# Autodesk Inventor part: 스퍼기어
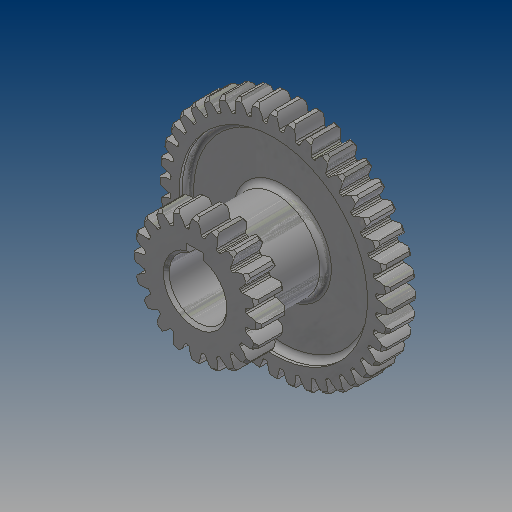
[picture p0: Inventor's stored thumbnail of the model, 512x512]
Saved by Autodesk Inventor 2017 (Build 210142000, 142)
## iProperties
Created: 2015-09
Part Number: 스퍼기어
Material: 강철, 연강
Document SubType Name: Modeling
Designer: mduedu
Density: 7.86 g/cm^3
Mass: 345.726 g
Surface Area: 225.641 cm^2
Volume: 43.9855 cm^3
Appearance: 강철
Author: mduedu
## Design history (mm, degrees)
sketch "스케치1"
  geometry: C1 r 38 at (0, 0); C2 r 40 at (0, 0); C3 r 35.5 at (0, 0); 1 further point
  constraints: 3 centre point, 3 coincident
  dimensions: "d0" = 76 diameter of C1; "d2" = 2 radial gap between concentric circles of C2 C1; "d3" = 71 diameter of C3 (computed from d0)
extrude "돌출1" new body sketch "스케치1" stored distance "d4" = 10; taper "d5" = 0 deg
sketch "스케치2"
  geometry: L1 (0, 35.5)-(0, -35.5); L2 (0, 0)-(40, 0); L3 (0, 0.57)-(39.996, 0.57); L4 (0, 1.57)-(39.969, 1.57); L5 (0, 2.07)-(39.946, 2.07); A1 r 35.5 centre (0, 0) between (0, 35.5) and (0, -35.5) reference; A2 r 40 centre (0, 0) between (40, 0) and (39.946, 2.07) reference; A3 r 9.234 centre (34.93, -7.149) between (39.996, 0.57) and (35.44, 2.07); A4 r 9.234 centre (34.93, 7.149) between (35.44, -2.07) and (39.996, -0.57); A5 r 40 centre (0, 0) between (39.996, -0.57) and (39.996, 0.57); A6 r 35.5 centre (0, 0) between (35.44, -2.07) and (35.44, 2.07); 4 further points
  constraints: 16 point on circle, 10 end point, 6 point on line, 4 centre point, 3 coincident, 3 parallel, 3 symmetric about line, 2 midpoint, 1 perpendicular, 1 vertical, 3 other
  dimensions: "d6" = 0.5 distance between parallel lines of L4 L5; "d8" = 1 distance between parallel lines of L3 L4; "d9" = 1.57 distance between parallel lines of L2 L4
extrude "돌출2" join sketch "스케치2" distance "d10" = 5; taper "d12" = 0 deg; dims "d11" = 5, "d13" = 0
fillet "모깎기1" dims "d17" = 0.5
chamfer "모따기1" distance "d21" = 1; stored, may be unused: second distance "d22" = 2, angle "d23" = 45 deg
sketch "스케치3"
  geometry: C1 r 32.5 at (0, 0); C2 r 15 at (0, 0); 1 further point
  constraints: 2 centre point, 2 coincident
  dimensions: "d27" = 65 diameter of C1; "d28" = 30 diameter of C2
extrude "돌출3" cut sketch "스케치3" distance "d29" = 3; taper "d30" = 0 deg
fillet "모깎기2" dims "d31" = 2
node "작업 평면2"
  node "작업 평면1"
sketch "스케치4"
  geometry: C1 r 15 at (0, 0) reference; 1 further point
extrude "돌출4" join sketch "스케치4" stored distance "d34" = 3; taper "d35" = 0 deg
sketch "스케치5"
  geometry: C1 r 17.5 at (0, 0); C2 r 20 at (0, 0); C3 r 22 at (0, 0); 1 further point
  constraints: 3 centre point, 3 coincident
  dimensions: "d36" = 40 diameter of C2; "d38" = 2 radial gap between concentric circles of C2 C3; "d39" = 35 diameter of C1 (= d36 - 2.5 x d38)
extrude "돌출6" join sketch "스케치5" distance "d46" = 10; taper "d47" = 0 deg
sketch "스케치6"
  geometry: L1 (0, 0)-(0, 22); L2 (-17.5, 0)-(17.5, 0); L3 (-0.57, 0)-(-0.57, 21.993); L4 (-1.57, 0)-(-1.57, 21.944); L5 (-2.07, 0)-(-2.07, 21.902); A1 r 22 centre (0, 0) between (0, 22) and (-0.57, 21.993) reference; A2 r 17.5 centre (0, 0) between (-17.5, 0) and (17.5, 0) reference; A3 r 9.431 centre (7.348, 16.868) between (-0.57, 21.993) and (-2.07, 17.377); A4 r 9.431 centre (-7.348, 16.868) between (2.07, 17.377) and (0.57, 21.993); A5 r 17.5 centre (0, 0) between (2.07, 17.377) and (-2.07, 17.377); A6 r 22 centre (0, 0) between (0.57, 21.993) and (-0.57, 21.993); 4 further points
  constraints: 16 point on circle, 10 end point, 5 point on line, 4 centre point, 3 coincident, 3 symmetric about line, 2 parallel, 2 perpendicular, 1 midpoint, 1 vertical, 3 other
  dimensions: "d40" = 0.5 distance between parallel lines of L4 L5; "d42" = 1 distance between parallel lines of L3 L4; "d43" = 1.57 distance between parallel lines of L1 L4
extrude "돌출5" join sketch "스케치6" distance "d44" = 10; taper "d45" = 0 deg
fillet "모깎기3" dims "d48" = 0.5
chamfer "모따기2" distance "d49" = 1; stored, may be unused: second distance "d50" = 2, angle "d51" = 45 deg
sketch "스케치7"
  geometry: C1 r 10 at (0, 0); 1 further point
  constraints: 1 centre point, 1 coincident
  dimensions: "d55" = 20 diameter of C1
extrude "돌출7" cut sketch "스케치7" stored distance "d56" = 10; taper "d57" = 0 deg
sketch "스케치8"
  geometry: L1 (-9.539, -3)-(-12.8, -3); L2 (-12.8, -3)-(-12.8, 3); L3 (-12.8, 3)-(-9.539, 3); L4 (-9.539, 3)-(-9.539, -3); A1 r 10 centre (0, 0) between (-9.539, -3) and (-9.539, 3) reference; 2 further points
  constraints: 8 end point, 3 point on circle, 2 parallel, 1 horizontal, 1 horizontal alignment, 1 perpendicular
  dimensions: "d58" = 6 distance of L1.end L2.end; "d60" = 22.8 distance from line of point (10, 0) L2
extrude "돌출8" cut sketch "스케치8" stored distance "d61" = 10; taper "d62" = 0 deg
chamfer "모따기3" distance "d63" = 1; stored, may be unused: second distance "d64" = 2, angle "d65" = 45 deg
fillet "모깎기4" dims "d66" = 2
node "솔리드1"
pattern_circular "원형 패턴3" dims angle "d25" = 360 deg
mirror "대칭1"
pattern_circular "원형 패턴4" dims angle "d53" = 360 deg
other parameters: "d32" = 5, "d33" = 42
